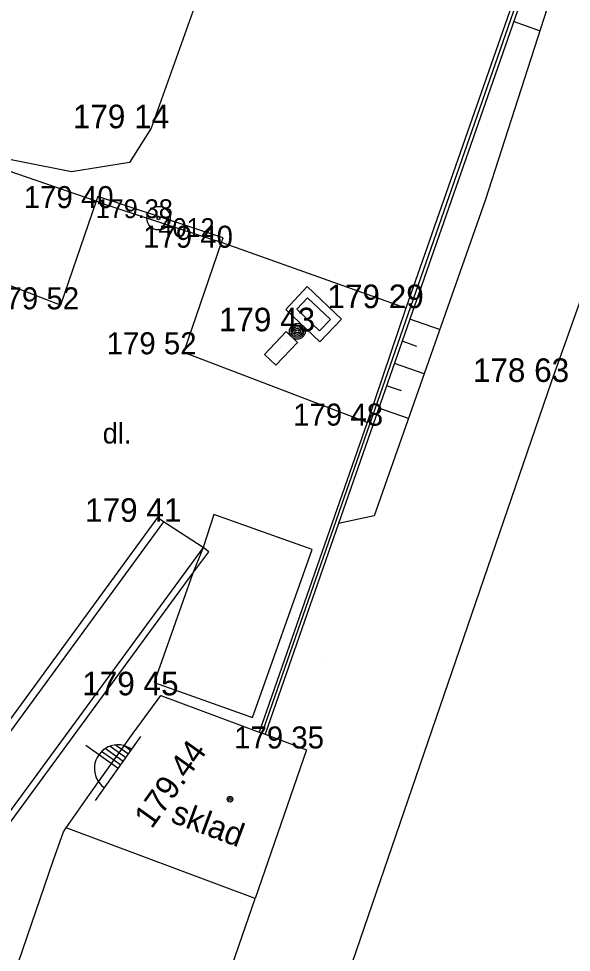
# Model space of a CAD drawing. Extents: x -537755 to -537431, y -1180722 to -1180510.
# Drawn here: x -537485.36 to -537467.76, y -1180620.59 to -1180590.89 of the extents above; entities that cross this region are included whole.
import ezdxf

# ---------------------------------------------------------------- set-up
doc = ezdxf.new("R2010")
doc.units = 0
for name, color, linetype in [('Vrstva 1', 7, 'Continuous'), ('Vrstva 10', 7, 'Continuous'), ('Vrstva 11', 7, 'Continuous'), ('Vrstva 12', 7, 'Continuous'), ('Vrstva 14', 7, 'Continuous'), ('Vrstva 15', 7, 'Continuous'), ('Vrstva 21', 7, 'Continuous'), ('Vrstva 22', 7, 'Continuous'), ('Vrstva 23', 7, 'Continuous'), ('Vrstva 24', 7, 'Continuous'), ('Vrstva 25', 7, 'Continuous'), ('Vrstva 3', 7, 'Continuous'), ('Vrstva 37', 7, 'Continuous'), ('Vrstva 39', 7, 'Continuous'), ('Vrstva 40', 7, 'Continuous'), ('Vrstva 41', 7, 'Continuous'), ('Vrstva 5', 7, 'Continuous'), ('Vrstva 6', 7, 'Continuous'), ('Vrstva 7', 7, 'Continuous'), ('Vrstva 8', 7, 'Continuous')]:
    doc.layers.add(name, color=color, linetype=linetype)

msp = doc.modelspace()

# ---------------------------------------------------------------- linework, layer by layer
at = {"layer": 'Vrstva 1'}
for p, q in [((-537470.58, -1180591.98), (-537470.58, -1180591.98)), ((-537481.14, -1180594.38), (-537481.14, -1180594.38)), ((-537481.83, -1180595.47), (-537481.83, -1180595.47)), ((-537483.68, -1180595.77), (-537483.68, -1180595.77)), ((-537482.87, -1180596.92), (-537482.87, -1180596.92)), ((-537470.51, -1180596.68), (-537470.51, -1180596.68)), ((-537479.07, -1180598.18), (-537479.07, -1180598.18)), ((-537483.97, -1180600.14), (-537483.97, -1180600.14)), ((-537473.031, -1180600.103), (-537473.031, -1180600.103)), ((-537471.81, -1180600.17), (-537471.81, -1180600.17)), ((-537476.49, -1180600.84), (-537476.49, -1180600.84)), ((-537480.23, -1180601.57), (-537480.23, -1180601.57)), ((-537468.4, -1180602.45), (-537468.4, -1180602.45)), ((-537474.29, -1180603.84), (-537474.29, -1180603.84)), ((-537474.04, -1180606.71), (-537474.04, -1180606.71)), ((-537480.75, -1180606.9), (-537480.75, -1180606.9)), ((-537479.49, -1180607.72), (-537479.49, -1180607.72)), ((-537475.59, -1180611.21), (-537475.59, -1180611.21)), ((-537477.05, -1180611.72), (-537477.05, -1180611.72)), ((-537480.84, -1180612.42), (-537480.84, -1180612.42)), ((-537481.72, -1180613.62), (-537481.72, -1180613.62)), ((-537476.2, -1180614.15), (-537476.2, -1180614.15)), ((-537476.17, -1180614.11), (-537476.17, -1180614.11)), ((-537483.11, -1180615.57), (-537483.11, -1180615.57)), ((-537483.94, -1180616.76), (-537483.94, -1180616.76)), ((-537484.27, -1180617.68), (-537484.27, -1180617.68))]:
    msp.add_line(p, q, dxfattribs=at)
at = {"layer": 'Vrstva 10'}
msp.add_line((-537474.268, -1180603.745), (-537480.104, -1180601.511), dxfattribs=at)
for points in [[(-537482.848, -1180596.551), (-537482.9, -1180596.702), (-537484.031, -1180600.009), (-537488.458, -1180598.296)], [(-537480.104, -1180601.511), (-537478.907, -1180598.018), (-537478.854, -1180597.863), (-537482.848, -1180596.551)]]:
    msp.add_lwpolyline(points, dxfattribs=at)
at = {"layer": 'Vrstva 11'}
for p, q in [((-537480.939, -1180606.762), (-537498.012, -1180630.027)), ((-537479.814, -1180608.536), (-537479.311, -1180607.851)), ((-537496.441, -1180631.179), (-537479.814, -1180608.536))]:
    msp.add_line(p, q, dxfattribs=at)
msp.add_lwpolyline([(-537479.311, -1180607.851), (-537479.49, -1180607.72), (-537480.75, -1180606.9), (-537480.939, -1180606.762)], dxfattribs=at)
at = {"layer": 'Vrstva 12'}
for p, q in [((-537480.75, -1180606.9), (-537497.9, -1180630.27)), ((-537479.49, -1180607.72), (-537496.71, -1180631.17))]:
    msp.add_line(p, q, dxfattribs=at)
at = {"layer": 'Vrstva 14'}
for p, q in [((-537468.22, -1180589.56), (-537470.51, -1180596.68)), ((-537470.51, -1180596.68), (-537474.04, -1180606.71)), ((-537474.04, -1180606.71), (-537475.176, -1180606.957))]:
    msp.add_line(p, q, dxfattribs=at)
at = {"layer": 'Vrstva 15'}
for p, q in [((-537468.773, -1180591.278), (-537469.605, -1180590.988)), ((-537471.961, -1180600.778), (-537472.906, -1180600.449)), ((-537472.68, -1180601.322), (-537473.153, -1180601.157)), ((-537472.455, -1180602.195), (-537473.4, -1180601.865)), ((-537473.175, -1180602.738), (-537473.647, -1180602.573)), ((-537472.949, -1180603.611), (-537473.894, -1180603.281))]:
    msp.add_line(p, q, dxfattribs=at)
at = {"layer": 'Vrstva 21'}
for radius in [0.375, 0.05]:
    msp.add_circle((-537480.91, -1180597.24), radius, dxfattribs=at)
at = {"layer": 'Vrstva 23'}
for p, q in [((-537475.54, -1180578.6), (-537481.14, -1180594.38)), ((-537481.14, -1180594.38), (-537481.83, -1180595.47))]:
    msp.add_line(p, q, dxfattribs=at)
msp.add_lwpolyline([(-537481.83, -1180595.47), (-537483.68, -1180595.77), (-537486.85, -1180595.14), (-537487.58, -1180594.58), (-537487.98, -1180592.38)], dxfattribs=at)
at = {"layer": 'Vrstva 24'}
for points in [[(-537476.861, -1180600.142), (-537475.774, -1180601.175), (-537475.085, -1180600.45), (-537476.172, -1180599.417)], [(-537476.508, -1180600.133), (-537475.783, -1180600.822), (-537475.438, -1180600.459), (-537476.163, -1180599.77)], [(-537476.844, -1180600.849), (-537477.533, -1180601.574), (-537477.17, -1180601.919), (-537476.481, -1180601.194)]]:
    msp.add_lwpolyline(points, close=True, dxfattribs=at)
at = {"layer": 'Vrstva 25'}
for radius in [0.25, 0.2, 0.15, 0.1, 0.05]:
    msp.add_circle((-537476.49, -1180600.84), radius, dxfattribs=at)
at = {"layer": 'Vrstva 37'}
for p, q in [((-537482.923, -1180615.767), (-537481.471, -1180613.733)), ((-537482.197, -1180614.75), (-537483.221, -1180614.019)), ((-537482.034, -1180614.522), (-537482.607, -1180614.113)), ((-537481.953, -1180614.408), (-537482.466, -1180614.042)), ((-537481.872, -1180614.294), (-537482.284, -1180614)), ((-537481.79, -1180614.18), (-537482.017, -1180614.019)), ((-537482.116, -1180614.636), (-537482.722, -1180614.203))]:
    msp.add_line(p, q, dxfattribs=at)
msp.add_arc((-537482.204, -1180614.745), 0.75, 53.856, 235.102, dxfattribs=at)
at = {"layer": 'Vrstva 39'}
for radius in [0.09, 0.0398]:
    msp.add_circle((-537478.634, -1180615.723), radius, dxfattribs=at)
at = {"layer": 'Vrstva 5'}
for p, q in [((-537479.15, -1180606.67), (-537479.49, -1180607.72)), ((-537476.02, -1180607.78), (-537479.15, -1180606.67)), ((-537479.49, -1180607.72), (-537479.814, -1180608.536)), ((-537477.921, -1180613.123), (-537476.02, -1180607.78)), ((-537479.814, -1180608.536), (-537481.05, -1180612.01)), ((-537481.05, -1180612.01), (-537477.921, -1180613.123)), ((-537481.72, -1180613.62), (-537480.84, -1180612.42)), ((-537480.84, -1180612.42), (-537477.702, -1180613.59)), ((-537477.702, -1180613.59), (-537477.608, -1180613.623)), ((-537477.608, -1180613.623), (-537477.515, -1180613.66)), ((-537477.515, -1180613.66), (-537476.2, -1180614.15)), ((-537476.2, -1180614.15), (-537477.831, -1180618.878)), ((-537483.85, -1180616.634), (-537483.11, -1180615.57)), ((-537484.27, -1180617.68), (-537483.94, -1180616.76)), ((-537483.94, -1180616.76), (-537483.85, -1180616.634)), ((-537477.831, -1180618.878), (-537483.85, -1180616.634)), ((-537481.145, -1180628.482), (-537477.831, -1180618.878))]:
    msp.add_line(p, q, dxfattribs=at)
at = {"layer": 'Vrstva 6'}
for p, q in [((-537483.11, -1180615.57), (-537481.72, -1180613.62)), ((-537485.36, -1180620.88), (-537484.27, -1180617.68))]:
    msp.add_line(p, q, dxfattribs=at)
at = {"layer": 'Vrstva 7'}
for p, q in [((-537461.41, -1180567.5), (-537475.176, -1180606.957)), ((-537477.608, -1180613.623), (-537461.55, -1180567.55)), ((-537461.663, -1180567.617), (-537473.031, -1180600.103)), ((-537468.4, -1180602.45), (-537462.2, -1180585.06)), ((-537482.9, -1180596.702), (-537490.201, -1180594.192)), ((-537482.79, -1180596.74), (-537482.9, -1180596.702)), ((-537478.907, -1180598.018), (-537479.1, -1180597.95)), ((-537473.031, -1180600.103), (-537478.907, -1180598.018)), ((-537473.031, -1180600.103), (-537474.268, -1180603.745)), ((-537475.39, -1180622.83), (-537468.4, -1180602.45)), ((-537474.268, -1180603.745), (-537477.702, -1180613.59)), ((-537475.176, -1180606.957), (-537477.515, -1180613.66))]:
    msp.add_line(p, q, dxfattribs=at)
at = {"layer": 'Vrstva 8'}
msp.add_line((-537482.79, -1180596.74), (-537479.1, -1180597.95), dxfattribs=at)

# ---------------------------------------------------------------- texts
at = {"layer": 'Vrstva 22'}
msp.add_text('179.38 ', height=0.6, dxfattribs=at).set_placement((-537482.91, -1180597.24))
at = {"layer": 'Vrstva 23'}
msp.add_text('4012', height=0.6, dxfattribs=at).set_placement((-537480.91, -1180597.84))
at = {"layer": 'Vrstva 3'}
for s, height, p in [('179 14 ', 0.75, (-537483.64, -1180594.38)), ('179 40 ', 0.7, (-537485.203, -1180596.92)), ('179 40 ', 0.7, (-537481.403, -1180598.18)), ('179 52 ', 0.7, (-537486.303, -1180600.14)), ('179 29 ', 0.75, (-537475.531, -1180600.103)), ('179 43 ', 0.75, (-537478.99, -1180600.84)), ('179 52 ', 0.7, (-537482.563, -1180601.57)), ('178 63 ', 0.75, (-537470.9, -1180602.45)), ('179 48 ', 0.7, (-537476.623, -1180603.84)), ('179 41 ', 0.75, (-537483.25, -1180606.9)), ('179 45 ', 0.75, (-537483.34, -1180612.42)), ('179 35 ', 0.7, (-537478.503, -1180614.11))]:
    msp.add_text(s, height=height, dxfattribs=at).set_placement(p)
at = {"layer": 'Vrstva 37'}
msp.add_text('179.44', height=0.75, rotation=54.4623, dxfattribs=at).set_placement((-537481.129, -1180616.695))
at = {"layer": 'Vrstva 40'}
msp.add_text('dl.', height=0.65, dxfattribs=at).set_placement((-537482.688, -1180604.409))
at = {"layer": 'Vrstva 41'}
msp.add_text('sklad', height=0.75, rotation=339.5523, dxfattribs=at).set_placement((-537480.558, -1180616.442))

doc.saveas('drawing.dxf')
